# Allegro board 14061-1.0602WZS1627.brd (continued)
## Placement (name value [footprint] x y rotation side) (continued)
Q6714  LMBT3904LT1G-GP  [SOT23CBE2D4H44]  98.05 120.17 270 top
Q6715  PMBS3904-1-GP  [SOT-23-10H44]  58.51 137.68 270 top
Q9624  AO3418L-GP  [SOT23DGS2D8H50]  20.18 206.12 0 bottom
Q9625  MMBT3904-4-GP  [SOT23CBE2D4H44]  101.63 92.46 90 top
Q9628  2N7002A-7-GP  [SOT23DGS2D4H48]  116.01 83.39 90 top
Q9629  AO3413L-GP  [SOT23DGS2D8H50]  110.26 83.24 0 top
Q9632  AO3413L-GP  [SOT23DGS2D8H50]  74.95 130.2 90 top
Q9634  DMN3052L-7-GP  [SOT23DGS2D4H48]  75.61 126.56 90 top
Q9635  LMBT3904LT1G-GP  [SOT23CBE2D4H44]  64.04 137.31 180 top
Q9636  2N7002A-7-GP  [SOT23DGS2D4H48]  71.96 133.78 270 top
Q9640  AO3413L-GP  [SOT23DGS2D8H50]  80.36 129.22 180 top
Q9641  AO3413L-GP  [SOT23DGS2D8H50]  80.35 133.24 180 top
Q9642  LMBT3904LT1G-GP  [SOT23CBE2D4H44]  74.04 137.46 270 top
Q9643  MMBT3904DW-GP  [SOT-363H44]  85.77 126.7 180 top
Q9646  2N7002KDW-GP  [SOT-363H44]  139.78 8.81 0 top
Q9647  AO3413L-GP  [SOT23DGS2D8H50]  41.71 110.34 180 bottom
Q9648  2N7002A-7-GP  [SOT23DGS2D4H48]  132.07 72.46 90 bottom
Q9649  AO3413L-GP  [SOT23DGS2D8H50]  139.44 71.73 90 bottom
Q9650  2N7002A-7-GP  [SOT23DGS2D4H48]  45.49 117.08 0 bottom
R5  -  [0R0402-PAD]  156.13 196.21 270 top
R7  10KR2J-3-GP  [R402H16]  154.21 196.28 90 top
R8  330R3J-L-GP  [R603H22]  38.46 109.15 90 bottom
R10  8K2R2J-3-GP  [R402H16]  128.81 214 0 bottom
R13  39K2R2F-L-GP  [R402H16]  127.8 214 180 bottom
R14  0R2J-2-GP  [R402H16]  122.08 220.47 270 top
R15  0R0402-PAD-2-GP  [0R0402-PAD-1]  133.89 215.14 0 bottom
R19  1MR2J-1-GP  [R402H16]  35.57 109.68 0 bottom
R20  470KR2F-GP  [R402H16]  38.9 118.95 180 bottom
R22  0R0402-PAD-2-GP  [0R0402-PAD-1]  104.17 215.14 270 top
R23  0R0402-PAD-2-GP  [0R0402-PAD-1]  104.17 216.15 270 top
R24  0R3J-0-U-GP  [R603H22]  157.46 186.82 270 bottom
R26  100KR2J-1-GP  [R402H16]  36.86 119.38 90 bottom
R27  D33R6F-GP  [R1206H26]  41.94 38.48 270 bottom
R30  100KR2J-1-GP  [R402H16]  36.86 118.32 90 bottom
R32  4K7R2J-2-GP  [R402H16]  39.58 86.51 0 bottom
R33  100KR2J-1-GP  [R402H16]  35.27 115.28 0 bottom
R34  0R0402-PAD-2-GP  [0R0402-PAD-1]  155.75 187.78 0 top
R35  0R0402-PAD-2-GP  [0R0402-PAD-1]  37.37 86.49 0 bottom
R37  0R1206-PAD-1-GP  [0R1206-PAD-1]  41 31.8 270 top
R39  22R2J-2-GP  [R402H16]  34.83 115.72 270 top
R41  10KR2J-3-GP  [R402H16]  33.82 113.67 90 bottom
R42  10KR2J-3-GP  [R402H16]  33.31 115.19 0 bottom
R43  220R2F-GP  [R402H16]  159.51 183.89 270 top
R44  10KR2J-3-GP  [R402H16]  44.97 121.72 270 top
R45  100R2F-L1-GP-U  [R402H14]  31.94 25.7 180 bottom
R46  1KR2J-1-GP  [R402H16]  134.55 203.45 180 top
R47  0R0402-PAD-2-GP  [0R0402-PAD-1]  162.52 203.22 0 bottom
R48  10KR2J-3-GP  [R402H16]  97.22 127.55 90 top
R49  10KR2J-3-GP  [R402H16]  98.71 127.47 0 top
R50  10KR2J-3-GP  [R402H16]  42.96 121.72 90 top
R51  10KR2J-3-GP  [R402H16]  93.02 123.7 270 top
R53  0R0402-PAD-2-GP  [0R0402-PAD-1]  26.02 32.36 270 bottom
R54  10KR2J-3-GP  [R402H16]  92 126.5 0 top
R55  2K2R2J-2-GP  [R402H16]  105.95 69.37 0 top
R56  10KR2J-3-GP  [R402H16]  104.73 69.37 180 top
R57  10KR2J-3-GP  [R402H16]  110.7 65.56 0 bottom
R58  10KR2J-3-GP  [R402H16]  26.91 15.44 270 top
R59  10KR2J-3-GP  [R402H16]  26.91 16.47 270 top
R60  10KR2J-3-GP  [R402H16]  28.96 13.91 90 bottom
R61  1KR2F-3-GP  [R402H16]  36.02 24.33 180 bottom
R62  10KR2J-3-GP  [R402H16]  104.6 120.55 180 top
R63  10KR2J-3-GP  [R402H16]  103.7 122.31 270 top
R64  1KR2J-1-GP  [R402H16]  18.63 188.11 270 top
R65  10KR2J-3-GP  [R402H16]  31.71 179.43 0 bottom
R66  10KR2J-3-GP  [R402H16]  109.72 120.19 0 top
R67  10KR2J-3-GP  [R402H16]  109.21 123 0 top
R68  100R2F-L1-GP-U  [R402H14]  15.7 201.35 180 top
R69  4K7R2J-2-GP  [R402H16]  47.02 78.28 0 top
R71  2K2R2J-2-GP  [R402H16]  15.68 203.3 0 top
R72  2K2R2J-2-GP  [R402H16]  25.76 176.79 270 bottom
R73  20KR2J-L2-GP  [R402H16]  19.23 204.43 270 top
R74  0R0402-PAD-2-GP  [0R0402-PAD-1]  19.34 201.83 180 top
R75  10KR2J-3-GP  [R402H16]  26.2 178.31 180 bottom
R76  8K2R2F-1-GP  [R402H16]  17.18 205.51 270 top
R80  4K7R2J-2-GP  [R402H16]  16.75 207.01 0 top
R81  10MR3F-GP  [R603H22]  56.55 153.64 0 top
R82  10KR2F-2-GP  [R402H16]  30.23 22.3 180 bottom
R86  0R0402-PAD-2-GP  [0R0402-PAD-1]  153.67 171.44 90 top
R87  20KR2F-L-GP  [R402H16]  153.67 170.39 90 top
R88  -  [0R0402-PAD]  153.73 174.35 90 top
R89  10KR2J-3-GP  [R402H16]  155.84 174.35 90 top
R91  20KR2F-L-GP  [R402H16]  153.99 180.53 90 top
R92  0R2J-2-GP  [R402H16]  155.61 170.43 90 top
R94  100KR2J-1-GP  [R402H16]  153.96 191.01 180 top
R95  10KR2J-3-GP  [R402H16]  34.04 207.75 90 bottom
R101  -  [0R0805-PAD]  17.77 211.54 90 top
R117  4K7R2F-GP  [R402H16]  131.07 148.29 180 bottom
R122  4K7R2F-GP  [R402H16]  139.05 146.96 0 bottom
R131  0R2J-2-GP  [R402H16]  36.27 117.07 90 top
R132  100KR2J-1-GP  [R402H16]  38.13 23.5 90 bottom
R133  4K7R2J-2-GP  [R402H16]  39.66 25.02 0 bottom
R134  10KR2J-3-GP  [R402H16]  40.09 23.5 90 bottom
R135  4K7R2J-2-GP  [R402H16]  38.13 25.73 90 top
R138  10KR2J-3-GP  [R402H16]  41.69 28.24 270 top
R139  4K7R2J-2-GP  [R402H16]  38.13 26.87 90 top
R143  1KR2J-1-GP  [R402H16]  38.44 23.57 270 top
R144  100KR2J-1-GP  [R402H16]  37.24 24.64 270 top
R146  2KR2J-1-GP  [R402H16]  127.74 65.74 90 bottom
R149  10KR2J-3-GP  [R402H16]  127.74 66.78 270 bottom
R151  100KR2J-1-GP  [R402H16]  152.6 207.45 270 top
R152  4K7R2J-2-GP  [R402H16]  148.47 223.77 180 top
R153  100KR2J-1-GP  [R402H16]  149.19 209.62 90 top
R155  100KR2J-1-GP  [R402H16]  155.84 108.27 90 bottom
R156  10KR2J-3-GP  [R402H16]  155.34 106.83 270 bottom
R157  -  [0R0805-PAD]  155.29 112.92 270 bottom
R158  10KR2J-3-GP  [R402H16]  155.67 111.4 90 bottom
R162  100KR2J-1-GP  [R402H16]  149.95 212 270 top
R163  47KR2J-2-GP  [R402H16]  149.19 210.95 90 top
R164  10KR2J-3-GP  [R402H16]  149.95 213.04 270 top
R169  10KR2J-3-GP  [R402H16]  32.65 135.39 90 top
R172  10KR2J-3-GP  [R402H16]  36.64 135.66 0 top
R174  619R2F-L1-GP  [R402H16]  164.4 116.14 0 bottom
R178  0R0402-PAD-2-GP  [0R0402-PAD-1]  95.42 116.46 90 top
R179  0R2J-2-GP  [R402H16]  158.2 102.53 180 bottom
R180  0R2J-2-GP  [R402H16]  158.2 104.43 180 bottom
R181  100KR2J-1-GP  [R402H16]  152.59 205.49 90 top
R183  -  [0R0805-PAD]  21.19 196.15 270 top
R184  10KR2J-3-GP  [R402H16]  94.92 117.65 90 top
R185  -  [0R0805-PAD]  21.16 194.09 270 top
R186  10KR2J-3-GP  [R402H16]  40.71 128.24 0 top
R199  1KR2J-1-GP  [R402H16]  137.31 17.21 180 top
R202  2K1R2F-GP  [R402H16]  48.04 114.05 0 top
R203  2K1R2F-GP  [R402H16]  49.21 114.02 180 top
R205  0R0402-PAD-2-GP  [0R0402-PAD-1]  154.9 46.99 270 bottom
R206  0R2J-2-GP  [R402H16]  154.9 45.9 270 bottom
R207  0R0402-PAD-2-GP  [0R0402-PAD-1]  151.32 53.04 180 top
R208  47KR2F-GP  [R402H16]  151.04 56.01 0 top
R209  33R2J-2-GP  [R402H16]  152.31 45.44 90 top
R210  47KR2F-GP  [R402H16]  152.1 56.01 180 top
R212  68R2F-GP  [R402H16]  156.54 194.74 180 top
R213  10KR2J-3-GP  [R402H16]  150.86 51.31 90 top
R215  0R0603-PAD-2-GP-U  [0R0603-PAD-1-U]  160.69 51.18 0 bottom
R216  0R3J-0-U-GP  [R603H22]  86.2 36.2 270 top
R220  10R2F-L-GP  [R402H14]  165.74 45.42 90 top
R221  10KR2J-3-GP  [R402H16]  170.09 77.98 180 top
R222  0R0402-PAD-2-GP  [0R0402-PAD-1]  155.58 42.34 180 top
R223  2K2R2J-2-GP  [R402H16]  154.47 55.75 180 top
R225  1KR2J-1-GP  [R402H16]  159.04 60.33 180 top
R230  2K1R2F-GP  [R402H16]  49.18 108.33 0 top
R261  2K2R2J-2-GP  [R402H16]  165.82 49.33 270 top
R262  2K2R2J-2-GP  [R402H16]  165.79 48.21 90 top
R266  10KR2F-2-GP  [R402H16]  165.82 51.64 270 top
R267  5K1R2F-2-GP  [R402H16]  165.82 52.7 270 top
R268  20KR2F-L-GP  [R402H16]  165.67 53.82 90 top
R269  4K7R2F-GP  [R402H16]  134.22 61.14 90 bottom
R270  10KR2F-2-GP  [R402H16]  137.82 50.3 0 top
R272  2K2R2J-2-GP  [R402H16]  165.82 50.52 270 top
R273  100KR2J-1-GP  [R402H16]  134.96 54.33 0 bottom
R274  20KR2J-L2-GP  [R402H16]  132.04 56.92 270 bottom
R275  10KR2F-2-GP  [R402H16]  139.09 50.3 0 top
R277  1KR2J-1-GP  [R402H16]  144.74 64.69 180 top
R278  1KR2J-1-GP  [R402H16]  144.31 66.17 270 top
R279  10KR2F-2-GP  [R402H16]  140.36 50.3 0 top
R280  0R0402-PAD-2-GP  [0R0402-PAD-1]  129.09 58.24 90 bottom
R281  10KR2J-3-GP  [R402H16]  170.09 80.01 0 top
R283  0R0402-PAD-2-GP  [0R0402-PAD-1]  138.84 65.1 180 top
R284  10R2F-L-GP  [R402H14]  165.77 46.81 90 top
R285  10KR2J-3-GP  [R402H16]  133.69 46.66 0 top
R286  10KR2J-3-GP  [R402H16]  134.22 58.75 270 bottom
R287  1KR2J-1-GP  [R402H16]  30.28 32.16 180 top
R289  0R3J-0-U-GP  [R603H22]  136.15 46.41 180 top
R293  1KR2J-1-GP  [R402H16]  137.73 64.52 180 top
R296  10KR2J-3-GP  [R402H16]  142.35 49.43 270 top
R297  10KR2J-3-GP  [R402H16]  122.61 53.34 270 bottom
R299  243R2F-2-GP  [R402H16]  48.44 97.76 90 top
R300  0R0603-PAD-2-GP-U  [0R0603-PAD-1-U]  157.64 40.41 90 top
R301  0R0603-PAD-2-GP-U  [0R0603-PAD-1-U]  161.83 65.58 45 top
R302  5K11R2F-L1-GP  [R402H16]  81.59 83.93 180 bottom
R303  10KR2J-3-GP  [R402H16]  134.32 50.92 0 top
R304  10KR2J-3-GP  [R402H16]  132.67 46.66 0 top
R305  0R0402-PAD-2-GP  [0R0402-PAD-1]  130.59 47.35 270 top
R306  1K5R3-GP  [R603H22]  167.7 91.29 0 top
R309  33R2J-2-GP  [R402H16]  135.11 64.75 270 top
R310  10KR2J-3-GP  [R402H16]  135.19 63.37 90 top
R311  10KR2J-3-GP  [R402H16]  135.19 62.33 90 top
R312  33R2J-2-GP  [R402H16]  135.19 61.24 90 top
R313  10KR2J-3-GP  [R402H16]  135.08 58.84 90 top
R314  1KR2J-1-GP  [R402H16]  154.21 48.95 90 bottom
R316  1KR2J-1-GP  [R402H16]  135.91 51.46 90 top
R317  10KR2J-3-GP  [R402H16]  99.68 76.23 180 top
R318  0R0402-PAD-2-GP  [0R0402-PAD-1]  129.37 70.38 0 top
R319  100KR2F-L1-GP  [R402H16]  151.09 52.25 270 bottom
R320  243R2F-2-GP  [R402H16]  48.47 94.67 90 top
R321  100KR2J-1-GP  [R402H16]  135.34 75.59 270 top
R322  1MR3F-GP  [R603H22]  150.73 54.13 0 bottom
R323  10KR2J-3-GP  [R402H16]  130.94 64.07 180 bottom
R324  4K7R2J-2-GP  [R402H16]  99.68 78.13 0 top
R329  8K2R2J-3-GP  [R402H16]  28.63 12.8 270 bottom
R330  10KR2J-3-GP  [R402H16]  125.71 62.33 180 bottom
R331  1KR2J-1-GP  [R402H16]  31.39 17.95 180 top
R332  15KR2F-GP  [R402H16]  31.45 19.84 180 top
R333  10KR2J-3-GP  [R402H16]  124.7 62.33 180 bottom
R335  10KR2J-3-GP  [R402H16]  125.94 46.84 0 top
R336  1KR2J-1-GP  [R402H16]  123.68 62.33 180 bottom
R337  33R2J-2-GP  [R402H16]  128.35 70.64 180 top
R338  100KR2J-1-GP  [R402H16]  125.28 70.76 0 top
R340  10KR2J-3-GP  [R402H16]  26.42 13.44 0 bottom
R342  10KR2J-3-GP  [R402H16]  138.85 12.93 180 top
R344  0R0603-PAD-2-GP-U  [0R0603-PAD-1-U]  159.34 26.49 270 top
R345  0R0603-PAD-2-GP-U  [0R0603-PAD-1-U]  161.07 39.75 270 top
R346  0R0603-PAD-2-GP-U  [0R0603-PAD-1-U]  163.47 34 0 top
R347  3K9R2F-GP  [R402H16]  159.47 28.04 180 top
R348  10KR2J-3-GP  [R402H16]  120.81 74.37 90 top
R351  75R3F-GP  [R603H22]  134.96 10.54 0 top
R352  75R3F-GP  [R603H22]  136.2 10.54 180 top
R354  10KR2F-2-GP  [R402H16]  128 46.81 0 top
R355  10K5R3F-GP  [R603H22]  161.07 37.21 270 top
R356  0R0603-PAD-2-GP-U  [0R0603-PAD-1-U]  161.07 38.48 90 top
R357  10KR2F-2-GP  [R402H16]  160.54 28.17 180 top
R358  5K6R2F-2-GP  [R402H16]  163.3 31.47 180 top
R359  0R0603-PAD-2-GP-U  [0R0603-PAD-1-U]  164.42 38.89 90 top
R360  100KR2J-1-GP  [R402H16]  160.82 35.18 90 top
R361  100KR2J-1-GP  [R402H16]  160.54 30.07 180 top
R362  10KR2J-3-GP  [R402H16]  131.48 6.02 270 top
R363  10KR2F-2-GP  [R402H16]  116 68.15 90 bottom
R364  10KR2J-3-GP  [R402H16]  129.55 6.02 270 top
R365  10K5R3F-GP  [R603H22]  164.4 36.35 270 top
R366  10KR2F-2-GP  [R402H16]  117.85 66.04 90 bottom
R367  0R0603-PAD-2-GP-U  [0R0603-PAD-1-U]  164.4 37.64 270 top
R368  1KR2J-1-GP  [R402H16]  30.23 19.91 0 bottom
R369  1MR3F-GP  [R603H22]  36.36 9.27 270 top
R370  10KR2F-2-GP  [R402H16]  29.12 24.96 270 bottom
R372  2KR2F-3-GP  [R402H16]  35.48 18.65 90 bottom
R373  33R2J-2-GP  [R402H16]  29.12 23.93 90 bottom
R374  -  [0R0402-PAD]  40.55 9.88 0 bottom
R375  1KR2J-1-GP  [R402H16]  112.48 55.78 270 top
R376  10R3J-3-GP  [R603H22]  155.51 37.41 90 top
R377  2K49R2F-GP  [R402H16]  39.12 9.8 180 top
R378  10KR2J-3-GP  [R402H16]  43.98 10.44 270 bottom
R379  0R2J-2-GP  [R402H16]  109.28 70.19 90 top
R380  0R2J-2-GP  [R402H16]  109.24 69.09 90 top
R381  0R0402-PAD-2-GP  [0R0402-PAD-1]  110.08 67.07 180 top
R382  100R2F-L1-GP-U  [R402H14]  111.77 66.13 270 top
R385  0R0402-PAD-2-GP  [0R0402-PAD-1]  111.87 59.97 270 top
R386  0R0402-PAD-2-GP  [0R0402-PAD-1]  113.18 58.95 270 top
R388  10KR2J-3-GP  [R402H16]  119.31 69.34 90 top
R389  4K7R2J-2-GP  [R402H16]  24.49 27.1 90 bottom
R390  10KR2J-3-GP  [R402H16]  111.82 57.92 270 top
R391  10KR2J-3-GP  [R402H16]  112.12 61.04 90 bottom
R392  2K2R2J-2-GP  [R402H16]  111.87 63.02 90 top
R393  33R2J-2-GP  [R402H16]  27.36 27.13 270 bottom
R394  2KR2F-3-GP  [R402H16]  92.87 101.6 180 bottom
R395  0R0402-PAD-2-GP  [0R0402-PAD-1]  110.95 62.1 90 bottom
R396  3D3R3F-GP  [R603H22]  146.59 7.37 0 top
R397  10KR2F-2-GP  [R402H16]  116.29 56.69 90 bottom
R398  10KR2J-L-GP  [R402H15]  69.08 84.73 180 top
R399  0R0402-PAD-2-GP  [0R0402-PAD-1]  124.62 55.14 90 bottom
R400  0R0402-PAD-2-GP  [0R0402-PAD-1]  124.62 54.1 90 bottom
R403  3D3R3F-GP  [R603H22]  146.59 10.03 180 top
R404  10KR2F-2-GP  [R402H16]  119.07 54.41 180 bottom
R415  3D3R3F-GP  [R603H22]  146.59 15.49 180 top
R419  3D3R3F-GP  [R603H22]  146.59 12.83 0 top
R421  10KR2J-3-GP  [R402H16]  46.11 34.75 0 top
R422  15KR2F-GP  [R402H16]  45.6 22.07 0 top
R424  100KR2J-1-GP  [R402H16]  46.69 22.07 180 top
R426  33R2J-2-GP  [R402H16]  44.53 22.07 180 top
R428  47R2J-2-GP  [R402H16]  86.29 32.44 90 top
R429  47R2J-2-GP  [R402H16]  84.26 32.41 90 top
R430  1K5R2J-3-GP  [R402H16]  45.75 33.27 90 top
R456  51R2J-2-GP  [R402H16]  138.62 203.43 0 top
R457  51R2J-2-GP  [R402H16]  139.63 203.43 0 top
R458  51R2J-2-GP  [R402H16]  139.99 206.1 0 top
R466  51R2J-2-GP  [R402H16]  152.51 202.45 270 bottom
R473  51R2J-2-GP  [R402H16]  137.6 203.43 0 top
R477  1KR2J-1-GP  [R402H16]  153.96 192.91 0 top
R481  10KR2J-3-GP  [R402H16]  42.37 104.14 270 bottom
R482  10KR2J-3-GP  [R402H16]  44.48 92.56 0 bottom
R483  4K7R2F-GP  [R402H16]  129.5 188.06 270 bottom
R484  4K7R2F-GP  [R402H16]  125.76 182.85 0 bottom
R492  20KR2J-L2-GP  [R402H16]  63.66 148.97 270 top
R498  10KR2J-3-GP  [R402H16]  77.81 185.01 180 top
R499  10KR2J-3-GP  [R402H16]  88.53 140.64 180 top
R501  100KR2J-1-GP  [R402H16]  39.1 118.85 90 top
R502  2K2R2J-2-GP  [R402H16]  43.62 23.42 180 bottom
R503  0R2J-2-GP  [R402H16]  38.25 117.07 90 top
R505  10KR2J-3-GP  [R402H16]  41.99 20.9 270 top
R507  0R0402-PAD-2-GP  [0R0402-PAD-1]  31.53 99.75 270 bottom
R510  10KR2J-3-GP  [R402H16]  88.27 150.27 270 bottom
R511  12KR2F-L-GP  [R402H16]  31.53 98.73 90 bottom
R512  100KR2J-1-GP  [R402H16]  31.53 87.04 90 bottom
R513  402R2F-GP  [R402H16]  69.68 165.08 270 bottom
R514  10KR2J-3-GP  [R402H16]  142.27 8.09 0 top
R515  0R0402-PAD-2-GP  [0R0402-PAD-1]  47.62 76.73 90 top
R516  10KR2J-3-GP  [R402H16]  42.15 23.77 90 bottom
R517  10KR2J-3-GP  [R402H16]  53.51 78.54 270 top
R519  402R2F-GP  [R402H16]  76.44 167.72 270 bottom
R523  10KR2J-3-GP  [R402H16]  48.06 78.28 180 top
R524  49D9R2F-GP  [R402H16]  76.31 162.08 270 bottom
R527  182R2F-GP  [R402H16]  98.33 159.26 0 top
R530  10KR2J-3-GP  [R402H16]  78.05 150.06 90 bottom
R531  10KR2J-3-GP  [R402H16]  63.48 77.47 180 top
R532  0R0402-PAD-2-GP  [0R0402-PAD-1]  150.73 127.28 270 bottom
R533  10KR2J-3-GP  [R402H16]  61.95 76.81 270 top
R535  4K7R2J-2-GP  [R402H16]  55.94 77.9 90 top
R536  -  [0R0402-PAD]  77.91 148.51 0 bottom
R537  10KR2F-L1-GP  [R402H15]  100.31 158.37 180 top
R539  0R0402-PAD-2-GP  [0R0402-PAD-1]  100.24 150.5 180 top
R542  4K7R2F-GP  [R402H16]  101.73 151.21 90 top
R543  10KR2F-L1-GP  [R402H15]  100.92 149 270 top
R544  1KR2J-1-GP  [R402H16]  153.7 185.17 90 top
R545  4K7R2F-GP  [R402H16]  101.73 150.06 270 top
R549  10KR2F-L1-GP  [R402H15]  154.92 129.31 90 bottom
R550  10KR2J-3-GP  [R402H16]  100.92 147.88 270 top
R551  10KR2F-L1-GP  [R402H15]  96.83 130.16 90 top
R552  10KR2J-3-GP  [R402H16]  82.94 150.06 180 bottom
R553  10KR2J-3-GP  [R402H16]  91.6 147.07 270 bottom
R554  10KR2J-3-GP  [R402H16]  83.12 147.55 0 bottom
R555  10KR2J-3-GP  [R402H16]  82.05 142.93 180 top
R556  10KR2J-3-GP  [R402H16]  92.26 148.41 270 top
R557  10KR2J-3-GP  [R402H16]  93.07 148.98 270 bottom
R558  10KR2J-3-GP  [R402H16]  82.99 140.69 180 top
R560  10KR2J-3-GP  [R402H16]  83.42 145.77 0 top
R561  10KR2J-3-GP  [R402H16]  91.15 148.97 270 bottom
R562  10KR2J-3-GP  [R402H16]  85.07 145.82 0 top
R563  10KR2J-3-GP  [R402H16]  84.03 143.46 90 top
R565  0R2J-2-GP  [R402H16]  159.72 137.57 90 bottom
R567  10KR2J-3-GP  [R402H16]  85.5 141.1 90 top
R569  10KR2J-3-GP  [R402H16]  155.34 105.79 270 bottom
R572  1KR2J-1-GP  [R402H16]  156.07 140.54 0 bottom
R576  10KR2J-3-GP  [R402H16]  161.83 140.56 0 top
R577  -  [0R0603-PAD]  159.49 114.59 180 top
R579  10KR2J-3-GP  [R402H16]  130.61 128.4 180 bottom
R581  10KR2J-3-GP  [R402H16]  127.67 128.42 180 bottom
R617  33KR2J-3-GP  [R402H16]  148.93 45.14 180 top
R618  0R2J-2-GP  [R402H16]  150.86 50.19 270 top
R627  1KR2J-1-GP  [R402H16]  157.18 60.4 180 top
R634  4K7R2J-2-GP  [R402H16]  153.96 39.09 270 bottom
R635  1KR2J-1-GP  [R402H16]  152.81 40.13 270 top
R636  10KR2J-3-GP  [R402H16]  152.03 39.09 90 bottom
R637  10KR2J-3-GP  [R402H16]  135.08 59.87 90 top
R639  20KR2J-L2-GP  [R402H16]  148.24 37.03 270 bottom
R642  2K2R2J-2-GP  [R402H16]  89.09 144.58 180 top
R643  20KR2J-L2-GP  [R402H16]  148.24 35.99 270 bottom
R644  330R3J-L-GP  [R603H22]  119.18 63.57 270 bottom
R645  10KR2J-3-GP  [R402H16]  85.06 132.82 180 top
R646  1KR2J-1-GP  [R402H16]  86.19 132.8 0 top
R648  17K8R2F-GP  [R402H16]  112.63 53.44 90 bottom
R649  6K49R2F-1-GP  [R402H16]  112.63 54.46 90 bottom
R650  17K8R2F-GP  [R402H16]  109.71 59.92 90 bottom
R651  0R0402-PAD-2-GP  [0R0402-PAD-1]  124.62 56.18 90 bottom
R652  0R0402-PAD-2-GP  [0R0402-PAD-1]  135.99 7.01 180 top
R653  10KR2F-2-GP  [R402H16]  110.4 49.56 90 top
R655  10KR2F-2-GP  [R402H16]  112.63 51.41 90 bottom
R656  10KR2F-2-GP  [R402H16]  112.63 56.49 90 bottom
R657  10KR2F-2-GP  [R402H16]  112.25 54.71 270 top
R658  10KR2F-2-GP  [R402H16]  116.29 57.84 90 bottom
R659  4K7R2J-2-GP  [R402H16]  134.96 7.06 180 top
R661  0R2J-2-GP  [R402H16]  133.41 7.14 270 top
R662  0R2J-2-GP  [R402H16]  111.87 62 90 top
R663  0R2J-2-GP  [R402H16]  137.46 12.84 0 top
R664  0R0402-PAD-2-GP  [0R0402-PAD-1]  76 141.91 270 top
R665  4K7R2J-2-GP  [R402H16]  133.41 6.1 270 top
R667  75R3F-GP  [R603H22]  137.45 10.54 180 top
R668  0R0402-PAD-2-GP  [0R0402-PAD-1]  111.87 60.99 90 top
R669  4K7R2J-2-GP  [R402H16]  123.18 67.54 90 bottom
R673  75R3F-GP  [R603H22]  136.69 8.59 90 top
R675  10KR2J-3-GP  [R402H16]  37.05 9.55 180 bottom
R676  100KR2J-1-GP  [R402H16]  116.06 60.15 270 bottom
R677  1KR2J-1-GP  [R402H16]  114.05 66.32 180 top
R680  1KR2J-1-GP  [R402H16]  24.52 26.04 270 bottom
R681  33R2J-2-GP  [R402H16]  27.36 26.06 270 bottom
R682  -  [0R0402-PAD]  24.52 24.99 90 bottom
R689  33R2J-2-GP  [R402H16]  27.36 28.17 270 bottom
R693  4K7R2J-2-GP  [R402H16]  25.46 29.39 90 bottom
R701  0R2J-2-GP  [R402H16]  45.4 6.07 180 bottom
R702  8K2R2J-3-GP  [R402H16]  46.41 6.07 180 bottom
R704  10KR2J-3-GP  [R402H16]  42.07 9.45 270 bottom
R705  8K2R2J-3-GP  [R402H16]  47.2 9.37 90 top
R706  39K2R2F-L-GP  [R402H16]  44.98 7.98 0 top
R707  10KR2J-3-GP  [R402H16]  41.77 5.82 270 top
R709  10KR2J-3-GP  [R402H16]  95.16 29.34 180 top
R717  10KR2J-3-GP  [R402H16]  100.92 121.46 90 top
R719  10KR2J-3-GP  [R402H16]  9.71 218.19 180 top
R720  4K7R2J-2-GP  [R402H16]  12.38 224.1 270 top
R721  2K2R2J-2-GP  [R402H16]  8.87 223.52 180 top
R722  10KR2J-3-GP  [R402H16]  6.59 223.04 0 top
R725  0R0402-PAD-2-GP  [0R0402-PAD-1]  141.31 46.33 0 top
R729  0R0402-PAD-2-GP  [0R0402-PAD-1]  153.88 178.18 90 top
R739  10KR2J-3-GP  [R402H16]  40.09 8.33 270 bottom
R870  243R2F-2-GP  [R402H16]  48.57 110.71 270 bottom
R885  2K1R2F-GP  [R402H16]  49.18 108.33 180 bottom
R886  2K1R2F-GP  [R402H16]  47.25 108.33 0 bottom
R899  243R2F-2-GP  [R402H16]  48.7 106.78 270 bottom
R924  2K1R2F-GP  [R402H16]  63.41 104.52 0 bottom
R928  2K1R2F-GP  [R402H16]  62.39 104.52 180 bottom
R935  4K53R2F-1-GP  [R402H16]  99.88 101.4 180 top
R940  2KR2F-3-GP  [R402H16]  102.17 101.24 0 top
R943  8K45R2F-2-GP  [R402H16]  95.34 103.4 270 bottom
R945  2K1R2F-GP  [R402H16]  49.13 96.29 0 bottom
R946  2K1R2F-GP  [R402H16]  48.08 96.26 180 bottom
R948  4K75R2F-1-GP  [R402H16]  93.02 103.58 0 bottom
R963  10KR2J-L-GP  [R402H15]  68.05 84.73 180 top
R1074  100KR2J-1-GP  [R402H16]  31.53 91.24 90 bottom
R1079  100KR2J-1-GP  [R402H16]  31.53 94.11 270 bottom
R1126  100KR2J-1-GP  [R402H16]  112.95 79.97 270 top
R1129  8K2R2J-3-GP  [R402H16]  112.98 81.41 270 top
R1154  0R2J-2-GP  [R402H16]  106.59 202.84 270 top
R1155  0R2J-2-GP  [R402H16]  104.17 218.19 270 top
R1158  1KR2F-3-GP  [R402H16]  81.87 92.71 90 bottom
R1159  10KR2J-L-GP  [R402H15]  99.4 106.78 0 top
R1160  -  [0R0402-PAD]  98.35 106.79 0 top
R1161  1K69R2F-2-GP  [R402H16]  85.97 112.65 0 bottom
R1162  1KR2F-3-GP  [R402H16]  87.02 112.64 0 bottom
R1163  1KR2F-3-GP  [R402H16]  42.36 105.52 270 bottom
R1164  100KR2J-1-GP  [R402H16]  72.22 115.47 0 top
R1165  0R0402-PAD-2-GP  [0R0402-PAD-1]  98.74 96.37 270 top
R1166  0R0402-PAD-2-GP  [0R0402-PAD-1]  97.54 93.32 270 top
R1167  10KR2J-3-GP  [R402H16]  107.5 79.17 90 top
R1168  33R2J-2-GP  [R402H16]  107.5 80.21 270 top
R1169  33R2J-2-GP  [R402H16]  107.5 81.28 270 top
R1170  33R2J-2-GP  [R402H16]  91.98 83.57 270 top
R1171  33R2J-2-GP  [R402H16]  93.94 84.1 270 top
R1182  0R0603-PAD-2-GP-U  [0R0603-PAD-1-U]  170.92 82.37 0 top
R1193  0R0603-PAD-2-GP-U  [0R0603-PAD-1-U]  154.39 59.44 90 top
R1195  39K2R2F-L-GP  [R402H16]  113.55 84.01 180 top
R1200  40D2R2F-GP  [R402H16]  76.87 114.73 180 bottom
R1201  120R2F-GP  [R402H16]  79.81 110.22 180 bottom
R1202  10R2F-L-GP  [R402H14]  84.13 89.9 180 bottom
R1203  0R0402-PAD-2-GP  [0R0402-PAD-1]  152.26 22.38 270 top
R1204  2K2R2J-2-GP  [R402H16]  85.17 87.99 180 bottom
R1205  4K99R2F-L-GP  [R402H16]  83.11 89.9 180 bottom
R1206  51D1R2F-GP  [R402H16]  77.55 81.78 0 top
R1207  51D1R2F-GP  [R402H16]  76.54 81.78 0 top
R1208  10KR2J-3-GP  [R402H16]  88.02 144.58 180 top
R1209  0R0402-PAD-2-GP  [0R0402-PAD-1]  104.17 217.17 90 top
R1210  249R2F-GP  [R402H16]  91.47 95.98 90 bottom
R1211  499R2F-2-GP  [R402H16]  91.47 94.54 270 bottom
R1214  0R0402-PAD-2-GP  [0R0402-PAD-1]  98.33 154.69 180 top
R1215  4K7R2F-GP  [R402H16]  98.33 152.65 180 top
R1216  4K7R2F-GP  [R402H16]  99.47 154.69 180 top
R1217  182R2F-GP  [R402H16]  99.47 152.65 0 top
R1223  -  [0R0805-PAD]  91.02 200.2 90 top
R1224  -  [0R0805-PAD]  91.02 198.22 90 top
R1225  -  [0R0805-PAD]  91.02 202.36 90 top
R1226  10KR2J-3-GP  [R402H16]  78.24 186.51 90 top
R1227  402R2F-GP  [R402H16]  73.1 174.41 270 bottom
R1228  402R2F-GP  [R402H16]  73.57 170.18 90 bottom
R1230  150R2F-1-GP  [R402H16]  77.26 174.6 270 bottom
R1234  0R2J-2-GP  [R402H16]  78.27 181.64 180 top
R1236  402R2F-GP  [R402H16]  72.8 168.91 90 bottom
R1239  200KR2F-L-GP  [R402H16]  55.89 162.97 0 top
R1240  0R0402-PAD-2-GP  [0R0402-PAD-1]  57.08 163.55 180 top
R1241  0R0402-PAD-2-GP  [0R0402-PAD-1]  57.74 161.62 0 top
R1242  2K49R2F-GP  [R402H16]  75.22 160.96 270 bottom
R1244  -  [0R0603-PAD]  92.66 161.96 90 bottom
R1245  -  [0R0603-PAD]  94.44 167.04 180 bottom
R1246  0R3J-0-U-GP  [R603H22]  67.78 144.9 90 top
R1247  -  [0R0603-PAD]  71.97 145.16 270 top
R1248  0R3J-0-U-GP  [R603H22]  86.22 146.38 90 bottom
R1249  0R3J-0-U-GP  [R603H22]  86.22 147.6 90 bottom
R1250  -  [0R0603-PAD]  79.14 148.09 0 bottom
R1251  -  [0R0603-PAD]  94.62 147.41 90 top
R1252  -  [0R0603-PAD]  77.2 179.9 225 bottom
R1253  -  [0R0603-PAD]  75.12 151.66 0 bottom
R1254  -  [0R0603-PAD]  71.35 150.91 90 bottom
R1255  -  [0R0603-PAD]  70.98 153.46 270 bottom
R1256  -  [0R0603-PAD]  65.11 158.75 0 top
R1257  10KR2J-3-GP  [R402H16]  74.48 155.43 0 bottom
R1258  0R0402-PAD-2-GP  [0R0402-PAD-1]  82.05 206.25 180 bottom
R1259  100R2F-L1-GP-U  [R402H14]  77.45 151.56 0 bottom
R1260  0R2J-2-GP  [R402H16]  109.79 62.38 0 top
R1261  0R2J-2-GP  [R402H16]  56.52 151.26 0 top
R1262  10KR2J-3-GP  [R402H16]  66.66 148.39 90 top
R1263  0R0402-PAD-2-GP  [0R0402-PAD-1]  73.25 157.13 90 bottom
R1264  0R0402-PAD-2-GP  [0R0402-PAD-1]  103.69 69.37 0 top
R1265  10KR2J-3-GP  [R402H16]  66.66 149.43 270 top
R1266  10KR2J-3-GP  [R402H16]  136.56 203.43 0 top
R1267  0R2J-2-GP  [R402H16]  67.83 156.79 180 top
R1268  0R2J-2-GP  [R402H16]  77.22 181.66 0 top
R1557  100KR2F-L1-GP  [R402H16]  103.56 198.35 180 bottom
R1558  100KR2F-L1-GP  [R402H16]  109.86 200.76 270 top
R1559  100KR2F-L1-GP  [R402H16]  106.71 200 270 top
R1560  100KR2F-L1-GP  [R402H16]  155.61 185.17 270 top
R1561  100KR2F-L1-GP  [R402H16]  91.22 200.51 180 bottom
R1562  4K7R2F-GP  [R402H16]  103.11 197.89 0 top
R1565  4K7R2F-GP  [R402H16]  96.22 198.42 180 bottom
R1568  10KR2J-3-GP  [R402H16]  141.1 206.12 0 top
R1569  0R0402-PAD-2-GP  [0R0402-PAD-1]  152.51 200.43 270 bottom
R1570  4K7R2F-GP  [R402H16]  101.33 197.89 0 top
R1571  0R0402-PAD-2-GP  [0R0402-PAD-1]  99.83 73.23 90 top
R1576  0R2J-2-GP  [R402H16]  94.05 129.58 180 top
R1577  0R2J-2-GP  [R402H16]  77.86 211.18 0 top
R1578  0R2J-2-GP  [R402H16]  89.04 129.62 180 top
R1579  10KR2J-3-GP  [R402H16]  90.34 123.61 90 top
R1580  10KR2J-3-GP  [R402H16]  90.95 126.49 0 top
R1581  10KR2J-3-GP  [R402H16]  90.59 130.03 90 top
R1582  10KR2J-3-GP  [R402H16]  92.52 130.03 90 top
R1584  0R0402-PAD-2-GP  [0R0402-PAD-1]  87.28 213.61 270 top
R1585  0R0402-PAD-2-GP  [0R0402-PAD-1]  87.28 215.9 270 top
R1586  0R0402-PAD-2-GP  [0R0402-PAD-1]  87.28 214.76 270 top
R1587  0R0402-PAD-2-GP  [0R0402-PAD-1]  87.28 217.04 270 top
R1588  0R0402-PAD-2-GP  [0R0402-PAD-1]  21.2 170.7 0 top
R1589  0R0402-PAD-2-GP  [0R0402-PAD-1]  22.28 169.93 0 top
R1591  0R2J-2-GP  [R402H16]  135.11 65.79 270 top
R1592  0R0402-PAD-2-GP  [0R0402-PAD-1]  112.48 56.85 90 top
R1593  0R0402-PAD-2-GP  [0R0402-PAD-1]  39.95 137.06 0 top
R1596  0R0402-PAD-2-GP  [0R0402-PAD-1]  154.8 21.79 270 top
R1597  0R0402-PAD-2-GP  [0R0402-PAD-1]  155.13 25.35 90 top
R1598  0R0402-PAD-2-GP  [0R0402-PAD-1]  159.16 36.5 180 top
R1599  0R0402-PAD-2-GP  [0R0402-PAD-1]  94.78 33.15 180 top
R1601  0R0402-PAD-2-GP  [0R0402-PAD-1]  102.36 131.02 90 top
R1602  0R0402-PAD-2-GP  [0R0402-PAD-1]  45.75 32.13 270 top
R1604  0R0402-PAD-2-GP  [0R0402-PAD-1]  82.3 210.69 270 bottom
R1606  0R0402-PAD-2-GP  [0R0402-PAD-1]  18.98 165.63 90 top
R1608  0R0402-PAD-2-GP  [0R0402-PAD-1]  104.17 213.11 270 top
R1609  0R0402-PAD-2-GP  [0R0402-PAD-1]  104.17 214.12 270 top
R1610  0R0402-PAD-2-GP  [0R0402-PAD-1]  104.17 211.07 270 top
R1611  0R0402-PAD-2-GP  [0R0402-PAD-1]  104.17 212.09 270 top
R1612  0R0402-PAD-2-GP  [0R0402-PAD-1]  104.17 219.2 270 top
R1615  10KR2J-3-GP  [R402H16]  133.89 219.2 0 bottom
R1620  0R2J-2-GP  [R402H16]  122.08 218.44 270 top
R1621  0R2J-2-GP  [R402H16]  122.13 217.4 270 top
R1622  0R2J-2-GP  [R402H16]  122.08 219.46 270 top
R1623  0R2J-2-GP  [R402H16]  122.08 221.49 270 top
R1627  0R0402-PAD-2-GP  [0R0402-PAD-1]  122.09 221.48 90 bottom
R1628  0R0402-PAD-2-GP  [0R0402-PAD-1]  104.17 220.22 270 top
R1633  10KR2J-3-GP  [R402H16]  120.3 206.38 0 bottom
R1634  0R5J-5-GP  [R805H24]  130.08 209.8 180 bottom
R1637  0R0402-PAD-2-GP  [0R0402-PAD-1]  106.59 203.89 90 top
R1647  20R2F-GP  [R402H16]  18.99 163.53 90 top
R1648  49D9R2F-GP  [R402H16]  17.51 163.09 0 top
R1653  20R2F-GP  [R402H16]  78.52 210.69 0 bottom
R1654  49D9R2F-GP  [R402H16]  77.38 210.69 0 bottom
R1656  10KR2J-3-GP  [R402H16]  163.79 140.53 0 top
R1661  10KR2J-3-GP  [R402H16]  66.24 143.32 180 top
R1668  0R0402-PAD-2-GP  [0R0402-PAD-1]  95.6 123.06 0 top
R1669  0R0402-PAD-2-GP  [0R0402-PAD-1]  101.63 129.11 0 top
R1670  0R0402-PAD-2-GP  [0R0402-PAD-1]  129.5 189.15 90 bottom
R1671  0R0402-PAD-2-GP  [0R0402-PAD-1]  140.58 146.53 90 bottom
R1672  0R0402-PAD-2-GP  [0R0402-PAD-1]  138.72 183.11 0 bottom
R1683  0R0402-PAD-2-GP  [0R0402-PAD-1]  153.03 214.2 180 top
R1687  8K2R2J-3-GP  [R402H16]  92.31 131.77 270 top
R1688  8K2R2J-3-GP  [R402H16]  100.57 119.02 180 top
R1689  0R0402-PAD-2-GP  [0R0402-PAD-1]  22.54 177.37 90 top
R1696  100KR2J-1-GP  [R402H16]  163.38 133.17 90 top
R1697  0R2J-2-GP  [R402H16]  88.86 142.65 180 top
R1714  10R2J-2-GP  [R402H14]  42.84 127.63 0 top
R1719  10KR2J-3-GP  [R402H16]  29.93 12.27 0 top
R1720  0R3J-0-U-GP  [R603H22]  24.68 5.69 270 bottom
R1729  10R2J-2-GP  [R402H14]  41.81 128.27 0 top
R1730  10R2J-2-GP  [R402H14]  34.95 137.66 90 top
R1731  10R2J-2-GP  [R402H14]  34.98 136.52 90 top
R1732  10R2J-2-GP  [R402H14]  43.33 124.58 0 top
R1733  33R2J-2-GP  [R402H16]  38.24 135.23 270 top
R1734  56D2R2F  [R402H16]  80.81 210.69 0 bottom
R1738  1KR2J-1-GP  [R402H16]  149.87 191.49 0 bottom
R1739  1KR2J-1-GP  [R402H16]  148.93 188.16 90 bottom
R1740  1KR2J-1-GP  [R402H16]  151.11 190.63 0 bottom
R1741  1KR2J-1-GP  [R402H16]  150.5 188.67 180 bottom
R1742  1KR2J-1-GP  [R402H16]  128.1 216.48 90 bottom
R1743  1KR2J-1-GP  [R402H16]  127.95 221.44 90 bottom
R1744  1KR2J-1-GP  [R402H16]  138.03 192.1 270 bottom
R1745  1KR2J-1-GP  [R402H16]  138.08 193.19 270 bottom
R1746  51R2J-2-GP  [R402H16]  161.96 179.02 270 top
R1747  0R0402-PAD-2-GP  [0R0402-PAD-1]  100.69 56.67 270 top
R1776  0R0402-PAD-2-GP  [0R0402-PAD-1]  100.69 57.81 270 top
R1778  0R0402-PAD-2-GP  [0R0402-PAD-1]  156.83 94.69 180 bottom
R1779  45D3R2F-L-GP  [R402H16]  71.23 171.51 90 bottom
R1780  10KR2J-3-GP  [R402H16]  94.79 148.77 90 top
R1782  10KR2J-3-GP  [R402H16]  104.68 221.74 180 top
R1784  470R2F-GP  [R402H16]  43.56 184.18 270 bottom
R1785  470R2F-GP  [R402H16]  50.36 182.75 90 bottom
R1786  470R2F-GP  [R402H16]  87.29 218.12 270 top
R1787  470R2F-GP  [R402H16]  50.58 179.12 90 bottom
R1788  470R2F-GP  [R402H16]  50.76 219.66 180 bottom
R1789  470R2F-GP  [R402H16]  42.22 179.17 270 top
R1790  470R2F-GP  [R402H16]  41.54 184.02 180 bottom
R1791  0R2J-2-GP  [R402H16]  66.69 177.62 270 top
R1792  1KR2J-1-GP  [R402H16]  88.17 147.73 180 bottom
R1793  1KR2J-1-GP  [R402H16]  85.38 148.72 270 bottom
R1794  1KR2J-1-GP  [R402H16]  85.12 150.19 180 bottom
R1795  1KR2J-1-GP  [R402H16]  87.41 140.64 0 top
R1796  1KR2J-1-GP  [R402H16]  85.33 142.16 270 top
R1797  1KR2J-1-GP  [R402H16]  84.03 140.69 0 top
R1798  1KR2J-1-GP  [R402H16]  81.95 139.55 0 top
R1799  1KR2J-1-GP  [R402H16]  80.88 139.55 0 top
R1800  1KR2J-1-GP  [R402H16]  79.84 139.55 0 top
R1801  10KR2F-2-GP  [R402H16]  103.11 195.86 0 top
R1802  10KR2F-2-GP  [R402H16]  101.33 195.86 0 top
R1803  10KR2F-2-GP  [R402H16]  101.89 198.35 180 bottom
R1804  10KR2F-2-GP  [R402H16]  101.89 200.38 180 bottom
R1805  10KR2F-2-GP  [R402H16]  100.01 200.41 180 bottom
R1806  10KR2F-2-GP  [R402H16]  100.01 198.37 180 bottom
R1807  10KR2F-2-GP  [R402H16]  91.22 198.48 180 bottom
R1808  10KR2F-2-GP  [R402H16]  104.3 195.83 0 top
R1809  10KR2F-2-GP  [R402H16]  104.3 197.87 0 top
R1810  10KR2F-2-GP  [R402H16]  98.28 200.43 180 bottom
R1811  10KR2F-2-GP  [R402H16]  98.28 198.4 180 bottom
R1812  10KR2F-2-GP  [R402H16]  96.22 200.46 180 bottom
R1813  10KR2F-2-GP  [R402H16]  94.8 200.48 180 bottom
R1814  10KR2F-2-GP  [R402H16]  94.8 198.45 180 bottom
R1815  10KR2F-2-GP  [R402H16]  92.72 200.48 180 bottom
R1816  10KR2F-2-GP  [R402H16]  92.72 198.45 180 bottom
R1817  10KR2F-2-GP  [R402H16]  108.21 200.41 180 bottom
R1818  10KR2F-2-GP  [R402H16]  103.56 200.38 180 bottom
R1819  10KR2F-2-GP  [R402H16]  109.3 200.41 180 bottom
R1820  10KR2J-3-GP  [R402H16]  152.76 204.11 90 top
R1822  100R2F-L1-GP-U  [R402H14]  85.06 212.01 180 top
R1823  100R2F-L1-GP-U  [R402H14]  84.36 215.65 270 top
R1826  100R2F-L1-GP-U  [R402H14]  20.11 170.7 0 top
R1827  100R2F-L1-GP-U  [R402H14]  23.32 169.93 180 top
R1830  20KR2J-L2-GP  [R402H16]  18.98 166.7 90 top
R1831  20KR2J-L2-GP  [R402H16]  20.84 163.78 0 top
R1832  100KR2J-1-GP  [R402H16]  163.38 131.04 90 top
R1835  0R0402-PAD-2-GP  [0R0402-PAD-1]  135.39 108.61 270 top
R1836  0R0402-PAD-2-GP  [0R0402-PAD-1]  35.85 180.59 0 bottom
R1837  0R0402-PAD-2-GP  [0R0402-PAD-1]  34.32 184.78 270 bottom
R1838  0R0402-PAD-2-GP  [0R0402-PAD-1]  80.13 220.97 90 top
R1839  0R0402-PAD-2-GP  [0R0402-PAD-1]  43.8 177.25 180 top
R1840  0R2J-2-GP  [R402H16]  48.4 223.08 270 top
R1841  0R2J-2-GP  [R402H16]  45.69 223.08 90 top
R1842  10KR2J-3-GP  [R402H16]  101.47 219.09 270 top
R1843  10KR2J-3-GP  [R402H16]  104.68 223.65 180 top
R1844  2K2R2J-2-GP  [R402H16]  107.81 223.22 0 bottom
R1845  20KR2J-L2-GP  [R402H16]  63.38 174.4 0 top
R1846  0R2J-2-GP  [R402H16]  64.39 174.4 0 top
R1867  10KR2J-3-GP  [R402H16]  111.84 48.11 0 top
R1868  10KR2J-3-GP  [R402H16]  113.55 47.35 270 top
R1870  10KR2J-3-GP  [R402H16]  116.8 46.86 90 top
R1879  1MR3F-GP  [R603H22]  98.48 109.71 180 top
R1880  10KR2J-3-GP  [R402H16]  103.46 100.66 180 top
R1881  10KR2J-3-GP  [R402H16]  102.01 98.81 270 top
R1882  10KR2J-3-GP  [R402H16]  81.59 82.02 180 top
R1883  4K7R2J-2-GP  [R402H16]  100.46 104.83 0 top
R1884  33R2J-2-GP  [R402H16]  97.06 89.41 180 top
R1885  10KR2J-3-GP  [R402H16]  97.57 87.88 270 top
R1886  10KR2J-3-GP  [R402H16]  81.59 83.93 0 top
R1887  10KR2J-3-GP  [R402H16]  97.59 85.45 270 top
R1888  100R2F-L1-GP-U  [R402H14]  79.03 112.27 270 bottom
R1889  100R2F-L1-GP-U  [R402H14]  75.15 113.59 90 bottom
R1890  40D2R2F-GP  [R402H16]  77.93 114.73 180 bottom
R1891  0R0402-PAD-2-GP  [0R0402-PAD-1]  151.75 132.44 270 bottom
R1892  0R2J-2-GP  [R402H16]  79.48 181.66 180 top
R1893  10KR2J-L-GP  [R402H15]  79.3 83.16 180 bottom
R1894  100KR2J-1-GP  [R402H16]  100.59 86.33 270 top
R1895  10KR2J-L-GP  [R402H15]  70.12 84.73 180 top
R1896  47KR2F-GP  [R402H16]  99.09 89.41 180 top
R1897  1KR2F-3-GP  [R402H16]  82.61 83.93 180 bottom
R1899  4K75R2F-1-GP  [R402H16]  98.2 99.72 90 top
R1900  8K45R2F-2-GP  [R402H16]  98.2 100.74 90 top
R1905  2K1R2F-GP  [R402H16]  47.02 108.33 180 top
R1906  40D2R2F-GP  [R402H16]  48.7 111.26 270 top
R1907  40D2R2F-GP  [R402H16]  48.7 112.37 270 top
R1908  40D2R2F-GP  [R402H16]  48.44 92.81 270 top
R1909  40D2R2F-GP  [R402H16]  48.44 91.66 270 top
R1910  10KR2J-3-GP  [R402H16]  78.24 187.61 270 top
R1911  2K1R2F-GP  [R402H16]  46.77 96.14 0 top
R1914  100KR2J-1-GP  [R402H16]  74.46 115.16 270 top
R1915  10KR2J-3-GP  [R402H16]  78.95 118.31 0 top
R1916  0R0402-PAD-2-GP  [0R0402-PAD-1]  78.96 116.33 0 top
R1917  1KR2J-1-GP  [R402H16]  84.16 118.08 0 top
R1918  470KR2F-GP  [R402H16]  72.65 116.94 270 top
R1919  1MR2J-1-GP  [R402H16]  77.81 119.2 180 top
R1920  0R2J-2-GP  [R402H16]  98.71 92.2 270 top
R1921  2K1R2F-GP  [R402H16]  48.29 91.19 0 bottom
R1922  2K1R2F-GP  [R402H16]  49.31 91.19 180 bottom
R1923  2K1R2F-GP  [R402H16]  48.44 93.82 270 bottom
R1924  2K1R2F-GP  [R402H16]  48.31 92.81 90 bottom
R1984  0R0402-PAD-2-GP  [0R0402-PAD-1]  34.21 117.07 270 top
R1985  0R0402-PAD-2-GP  [0R0402-PAD-1]  38.13 27.94 90 top
R2079  0R2J-2-GP  [R402H16]  44.79 74.27 90 bottom
R2080  0R0402-PAD-2-GP  [0R0402-PAD-1]  49.33 74.32 90 bottom
R3586  0R0402-PAD-2-GP  [0R0402-PAD-1]  126.54 41.08 0 top
R5290  10KR2J-3-GP  [R402H16]  43.54 183.09 270 bottom
R6701  0R3J-0-U-GP  [R603H22]  88.15 81.41 270 top
R6702  10KR2J-3-GP  [R402H16]  88.98 79.83 0 top
R6703  100KR2J-1-GP  [R402H16]  21.72 185.78 180 top
R6704  100KR2J-1-GP  [R402H16]  88.7 74.96 270 top
R6705  100KR2J-1-GP  [R402H16]  20.25 190.2 0 top
R6706  0R2J-2-GP  [R402H16]  16.02 185.8 0 top
R79612  75R3F-GP  [R603H22]  63.28 11.94 270 top
R79618  0R0402-PAD-2-GP  [0R0402-PAD-1]  84.64 25.07 0 top
R79621  10KR2F-2-GP  [R402H16]  38.13 26.42 270 bottom
R79622  D33R6F-GP  [R1206H26]  41.94 36.2 270 bottom
R79623  300KR2F-GP  [R402H16]  38.2 27.5 270 bottom
R79625  10KR2F-2-GP  [R402H16]  41.7 30.19 90 top
R79627  300KR2F-GP  [R402H16]  38.79 29.72 180 top
R79628  100KR2F-L1-GP  [R402H16]  34.07 24.31 180 bottom
R79630  200R5J-GP  [R805H24]  34.75 35.18 180 bottom
R79631  0R1206-PAD-1-GP  [0R1206-PAD-1]  42.15 40.28 270 top
R79633  0R0402-PAD-2-GP  [0R0402-PAD-1]  34.81 25.15 0 top
R79634  0R0402-PAD-2-GP  [0R0402-PAD-1]  33.74 25.12 0 top
R79656  100R2F-L1-GP-U  [R402H14]  45.27 109.02 180 bottom
R79657  10KR2J-3-GP  [R402H16]  42.46 119.91 180 bottom
R79658  80D6R2F-L-GP  [R402H16]  77.15 154.58 180 bottom
R79659  10KR2J-3-GP  [R402H16]  161.01 125.32 180 top
R79660  0R0402-PAD-2-GP  [0R0402-PAD-1]  159.95 125.32 180 top
R79661  1KR2F-3-GP  [R402H16]  43.56 119.91 180 bottom
R79662  10KR2J-3-GP  [R402H16]  79.39 143.2 180 top
R79664  0R2J-2-GP  [R402H16]  32.6 61.17 270 bottom
R79665  0R2J-2-GP  [R402H16]  32.91 58.84 0 bottom
R79666  10KR2J-3-GP  [R402H16]  126.96 46.84 0 top
R79667  10KR2J-3-GP  [R402H16]  127.77 53.77 270 bottom
R79668  0R0402-PAD-2-GP  [0R0402-PAD-1]  36.1 86.49 0 bottom
R79669  4K7R2J-2-GP  [R402H16]  42.25 79.43 180 bottom
R79670  4K7R2J-2-GP  [R402H16]  61.95 77.93 270 top
R79673  4K7R2J-2-GP  [R402H16]  35.09 86.49 0 bottom
R79675  1KR2J-1-GP  [R402H16]  31.53 89.15 90 bottom
R79677  4K7R2J-2-GP  [R402H16]  31.54 84.02 270 bottom
R79678  4K7R2J-2-GP  [R402H16]  31.53 85.06 270 bottom
R79679  4K7R2J-2-GP  [R402H16]  30.26 77.29 180 bottom
R79680  10KR2J-3-GP  [R402H16]  31.54 88.09 90 bottom
R79681  100KR2J-1-GP  [R402H16]  31.53 90.17 90 bottom
R79682  0R2J-2-GP  [R402H16]  42.82 114.59 180 top
R79683  10KR2J-3-GP  [R402H16]  53.51 77.44 270 top
R79684  0R0402-PAD-2-GP  [0R0402-PAD-1]  44.8 75.41 90 bottom
R79685  0R0402-PAD-2-GP  [0R0402-PAD-1]  45.07 77.55 90 bottom
R79686  4K7R2J-2-GP  [R402H16]  44.41 78.33 0 top
R79687  10KR2J-3-GP  [R402H16]  51.21 75.74 270 top
R79688  10KR2J-3-GP  [R402H16]  87.32 139.05 90 top
R79689  10KR2J-3-GP  [R402H16]  132.04 64.07 180 bottom
R79690  2K2R2J-2-GP  [R402H16]  83.95 132.82 180 top
R79691  -  [0R0603-PAD]  134.88 46.41 0 top
R79692  10KR2F-2-GP  [R402H16]  139.66 60.3 180 top
R79693  10KR2F-2-GP  [R402H16]  140.88 60.3 180 top
R79694  10KR2F-2-GP  [R402H16]  142.1 60.3 180 top
R79697  0R2J-2-GP  [R402H16]  142.82 78.59 90 bottom
R79698  0R2J-2-GP  [R402H16]  145.6 80.87 270 top
R79699  0R2J-2-GP  [R402H16]  145.6 81.99 270 top
R79700  0R2J-2-GP  [R402H16]  145.58 83.11 270 top
R79701  10KR2J-3-GP  [R402H16]  161.55 109.28 0 top
R79702  10KR2J-3-GP  [R402H16]  158.8 108.38 90 top
R79703  10KR2J-3-GP  [R402H16]  159.44 107.24 270 bottom
R79704  10KR2J-3-GP  [R402H16]  121.98 47.07 0 top
R79705  10KR2J-3-GP  [R402H16]  120.91 47.07 0 top
R79707  0R5J-5-GP  [R805H24]  59.85 37.72 90 bottom
R79708  0R5J-5-GP  [R805H24]  58.15 47.05 270 top
R79709  0R5J-5-GP  [R805H24]  59.85 39.75 90 bottom
R79710  0R5J-5-GP  [R805H24]  59.85 41.78 90 bottom
R79711  0R5J-5-GP  [R805H24]  59.85 43.81 90 bottom
R79712  0R0402-PAD-2-GP  [0R0402-PAD-1]  27.92 32.82 270 bottom
R79713  0R0402-PAD-2-GP  [0R0402-PAD-1]  27.92 31.6 270 bottom
R79714  0R5J-5-GP  [R805H24]  38.01 35.15 180 bottom
R79715  0R0402-PAD-2-GP  [0R0402-PAD-1]  26.02 30.96 270 bottom
R79716  10R2F-L-GP  [R402H14]  38.2 30.99 90 bottom
R79717  1KR2J-1-GP  [R402H16]  33.69 31.72 180 top
R79718  1KR2J-1-GP  [R402H16]  30.51 29.16 180 top
R79719  10KR2J-3-GP  [R402H16]  31.5 32.61 180 top
R79720  10KR2J-3-GP  [R402H16]  29.63 30.7 90 top
R79721  10KR2J-3-GP  [R402H16]  32.55 32.61 180 top
R79722  100KR2F-L1-GP  [R402H16]  147.94 73.55 90 bottom
R79723  100KR2J-1-GP  [R402H16]  146 32.64 90 bottom
R79724  470R2J-2-GP  [R402H16]  138.95 31.06 270 bottom
R79725  470R2J-2-GP  [R402H16]  138.95 35 270 bottom
R79726  470R2J-2-GP  [R402H16]  138.95 28.14 270 bottom
R79727  470R2J-2-GP  [R402H16]  138.95 38.94 270 bottom
R79728  470R2J-2-GP  [R402H16]  138.95 32.08 270 bottom
R79729  470R2J-2-GP  [R402H16]  138.95 36.02 270 bottom
R79730  470R2J-2-GP  [R402H16]  138.89 42.85 270 bottom
R79731  470R2J-2-GP  [R402H16]  138.95 39.95 270 bottom
R79732  2K2R2J-2-GP  [R402H16]  130.22 29.41 270 top
R79733  2K2R2J-2-GP  [R402H16]  128.24 29.41 90 top
R79734  4K7R2F-GP  [R402H16]  131.72 41.54 0 bottom
R79735  4K7R2F-GP  [R402H16]  131.72 41.54 0 top
R79736  2K2R2J-2-GP  [R402H16]  134.9 29.62 180 top
R79737  2K2R2J-2-GP  [R402H16]  135.94 29.62 180 top
R79738  2K2R2J-2-GP  [R402H16]  128.24 30.56 270 top
R79739  2K2R2J-2-GP  [R402H16]  130.22 30.56 90 top
R79741  4K7R2F-GP  [R402H16]  132.28 28.3 90 top
R79742  4K7R2F-GP  [R402H16]  132.28 27.18 270 top
R79743  4K7R2F-GP  [R402H16]  133.78 41.54 0 bottom
R79744  4K7R2F-GP  [R402H16]  133.78 41.54 0 top
R79745  4K7R2F-GP  [R402H16]  132.74 41.54 0 bottom
R79746  4K7R2F-GP  [R402H16]  132.74 41.54 0 top
R79747  4D3KR2F-GP  [R402H16]  130.71 41.54 180 top
R79748  4K7R2F-GP  [R402H16]  128.78 41.54 0 top
R79749  4K7R2F-GP  [R402H16]  134.9 41.54 0 top
R79750  10KR2J-3-GP  [R402H16]  129.9 22.86 0 bottom
R79751  180R3F-GP  [R603H22]  123.45 18.82 270 bottom
R79752  36R3F-GP  [R603H22]  126.27 19.18 270 bottom
R79753  0R3J-0-U-GP  [R603H22]  159.75 192.68 90 bottom
R79754  10KR5F-2-GP  [R805H24]  25.56 10.97 270 bottom
R79755  0R2J-2-GP  [R402H16]  54.45 136.52 90 top
R79756  0R2J-2-GP  [R402H16]  89.09 77.14 180 top
R79757  100KR2J-1-GP  [R402H16]  16.02 187.71 180 top
R79758  10KR2J-3-GP  [R402H16]  44.66 119.93 0 bottom
R79759  1KR2J-1-GP  [R402H16]  135.24 55.73 90 top
R79761  1KR2J-1-GP  [R402H16]  135.03 54.23 180 top
R79762  1KR2J-1-GP  [R402H16]  135.08 57.81 90 top
R79763  1KR2J-1-GP  [R402H16]  135.08 56.77 90 top
R79764  2K2R2J-2-GP  [R402H16]  92.46 36.2 90 top
R79765  10KR2J-3-GP  [R402H16]  91.55 37.85 0 top
R79766  1KR2J-1-GP  [R402H16]  129.04 46.81 0 top
R79772  1KR2J-1-GP  [R402H16]  138.5 63.04 90 top
R79773  10KR2J-3-GP  [R402H16]  128.96 60.33 0 bottom
R79774  20KR2J-L2-GP  [R402H16]  136.58 66.12 180 top
R79780  10KR2F-2-GP  [R402H16]  127.92 60.33 0 bottom
R79781  10KR2J-3-GP  [R402H16]  110.32 57.51 0 top
R79785  113R2F-GP  [R402H16]  66.68 176.56 270 top
R79786  20KR2J-L2-GP  [R402H16]  83.52 209.19 0 bottom
R79787  100R2F-L1-GP-U  [R402H14]  82.82 172.85 180 bottom
R79788  100R2F-L1-GP-U  [R402H14]  75.53 155.43 180 bottom
R79790  200R2F-L-GP  [R402H16]  76.28 210.69 0 bottom
R79791  200R2F-L-GP  [R402H16]  78.77 181.53 180 bottom
R79792  200R2F-L-GP  [R402H16]  19.36 160.16 90 top
R79793  301R2F-GP  [R402H16]  18.98 164.58 270 top
R79794  301R2F-GP  [R402H16]  79.66 210.69 0 bottom
R79795  200R2F-L-GP  [R402H16]  75.71 208.74 0 bottom
R79796  47KR2F-GP  [R402H16]  99.25 222.85 180 top
R79797  10KR2J-3-GP  [R402H16]  69.08 160.58 0 bottom
R79798  2K2R2J-2-GP  [R402H16]  54.22 139.51 90 top
R79799  10KR2J-3-GP  [R402H16]  54.22 138.45 270 top
R79800  51KR2F-L-GP  [R402H16]  97.22 223.92 180 top
R79802  59KR2F-GP  [R402H16]  136.05 109.72 90 bottom
R79913  0R2J-2-GP  [R402H16]  22.79 193.5 270 bottom
R79914  4K7R2J-2-GP  [R402H16]  18.96 207.14 0 top
R79915  47KR2J-2-GP  [R402H16]  18.96 197.51 270 bottom
R79916  100KR2J-1-GP  [R402H16]  18.96 198.55 90 bottom
R79917  10KR2J-3-GP  [R402H16]  21.75 201.17 0 bottom
R79935  -  [0R0805-PAD]  21.24 206.32 180 top
R79936  10KR2J-3-GP  [R402H16]  20.28 193.5 270 bottom
R79937  200R2F-L-GP  [R402H16]  17.94 161.58 270 top
R79938  0R2J-2-GP  [R402H16]  119.64 61.57 90 bottom
R79939  0R0402-PAD-2-GP  [0R0402-PAD-1]  120.98 69.65 0 top
R79940  33R2J-2-GP  [R402H16]  47.87 71.43 90 bottom
R79941  33R2J-2-GP  [R402H16]  47.87 70.39 90 bottom
R79942  33R2J-2-GP  [R402H16]  32.14 65.37 180 bottom
R79943  10KR2J-3-GP  [R402H16]  157.56 106.32 0 bottom
R79944  10KR2J-3-GP  [R402H16]  157.13 181.79 0 top
R79945  10KR2J-3-GP  [R402H16]  123.25 64.49 270 bottom
R79946  0R2J-2-GP  [R402H16]  143.19 61.14 0 top
R79947  0R2J-2-GP  [R402H16]  129.83 55.24 270 bottom
R79948  0R2J-2-GP  [R402H16]  113.34 62.66 180 top
R79949  0R0402-PAD-2-GP  [0R0402-PAD-1]  14.96 224.08 90 top
R79950  0R0402-PAD-2-GP  [0R0402-PAD-1]  114.56 55.5 0 bottom
R79951  0R2J-2-GP  [R402H16]  122.11 69.62 0 top
R79952  10KR2J-3-GP  [R402H16]  123.47 58.54 0 bottom
R79953  10KR2J-3-GP  [R402H16]  124.51 58.54 0 bottom
R79954  0R2J-2-GP  [R402H16]  145.58 84.12 270 top
R79955  0R2J-2-GP  [R402H16]  145.58 85.14 270 top
R79956  0R2J-2-GP  [R402H16]  145.58 86.21 270 top
R79957  0R2J-2-GP  [R402H16]  150.22 77.85 180 top
R79960  0R2J-2-GP  [R402H16]  145.6 87.25 270 top
R79961  0R2J-2-GP  [R402H16]  145.6 88.29 270 top
R79962  47R2J-2-GP  [R402H16]  84.13 87.99 180 bottom
R79963  8K45R2F-2-GP  [R402H16]  95.27 101.98 270 bottom
R79964  0R2J-2-GP  [R402H16]  98.71 91.19 90 top
R79965  10KR2J-L-GP  [R402H15]  80.47 83.14 180 bottom
R79966  47KR2F-GP  [R402H16]  99.61 87.95 270 top
R79967  2K2R2J-2-GP  [R402H16]  100.11 89.41 180 top
R79968  2K1R2F-GP  [R402H16]  48.76 96.15 180 top
R79977  0R0402-PAD-2-GP  [0R0402-PAD-1]  163.38 135.25 270 top
R79980  0R0402-PAD-2-GP  [0R0402-PAD-1]  163.15 137.13 270 top
R79981  0R0402-PAD-2-GP  [0R0402-PAD-1]  162.82 153.11 90 top
R79982  0R0402-PAD-2-GP  [0R0402-PAD-1]  162.82 151.71 90 top
R80049  20KR2F-L-GP  [R402H16]  144.15 116.43 180 top
R80050  0R0402-PAD-2-GP  [0R0402-PAD-1]  141.66 113.39 270 top
R80051  0R0402-PAD-2-GP  [0R0402-PAD-1]  145.17 114.71 270 bottom
R80052  0R0402-PAD-2-GP  [0R0402-PAD-1]  141.66 112.34 270 top
R80053  0R0402-PAD-2-GP  [0R0402-PAD-1]  145.19 113.67 270 bottom
R80054  0R2J-2-GP  [R402H16]  160.79 133.99 180 top
R80055  0R2J-2-GP  [R402H16]  160.74 131.98 90 top
R80056  0R2J-2-GP  [R402H16]  160.94 151.38 180 top
R80057  0R2J-2-GP  [R402H16]  160.97 147.9 180 top
R80059  0R2J-2-GP  [R402H16]  141.81 109.17 270 top
R80060  33KR2F-GP  [R402H16]  145.19 117.3 180 top
R80061  0R2J-2-GP  [R402H16]  146.24 116.64 180 top
R80062  10KR2J-3-GP  [R402H16]  144.56 108.92 0 top
R80063  0R2J-2-GP  [R402H16]  145.04 105.98 270 top
R80064  0R2J-2-GP  [R402H16]  146.99 106.94 0 top
R80065  0R2J-2-GP  [R402H16]  147.76 108.92 0 top
R80074  0R2J-2-GP  [R402H16]  49.07 137.6 180 top
R80075  0R2J-2-GP  [R402H16]  48 137.6 180 top
R80076  0R2J-2-GP  [R402H16]  46.91 137.6 180 top
R80077  0R2J-2-GP  [R402H16]  45.86 137.6 180 top
R80078  0R2J-2-GP  [R402H16]  47.75 134.3 0 bottom
R80079  0R2J-2-GP  [R402H16]  48.89 134.3 0 bottom
R80080  0R2J-2-GP  [R402H16]  45.54 134.33 0 bottom
R80081  0R2J-2-GP  [R402H16]  46.68 134.33 0 bottom
R80090  0R2J-2-GP  [R402H16]  51.24 134.29 0 bottom
R80091  0R2J-2-GP  [R402H16]  50.06 134.29 0 bottom
R80092  0R0402-PAD-2-GP  [0R0402-PAD-1]  132.27 32.05 270 bottom
R80093  0R0402-PAD-2-GP  [0R0402-PAD-1]  134.81 29.64 0 bottom
R80099  0R2J-2-GP  [R402H16]  51.18 137.6 0 top
R80100  0R2J-2-GP  [R402H16]  50.12 137.6 0 top
R80102  100KR2F-L1-GP  [R402H16]  43.29 222.12 90 top
R80103  0R0402-PAD-2-GP  [0R0402-PAD-1]  163.23 147.88 0 top
R80104  0R0402-PAD-2-GP  [0R0402-PAD-1]  163.28 138.68 270 top
R80105  0R0402-PAD-2-GP  [0R0402-PAD-1]  163.38 132.11 90 top
R80106  0R0402-PAD-2-GP  [0R0402-PAD-1]  163.3 156.11 180 top
R80107  0R2J-2-GP  [R402H16]  160.17 143.63 180 top
R80108  0R2J-2-GP  [R402H16]  160.75 136.68 180 top
R80109  0R2J-2-GP  [R402H16]  160.05 130.35 90 top
R80110  2K2R2J-2-GP  [R402H16]  129.81 28.76 180 bottom
R80111  2K2R2J-2-GP  [R402H16]  133.77 26.71 180 bottom
R80112  1MR2J-1-GP  [R402H16]  127.63 41.08 0 top
R80113  0R2J-2-GP  [R402H16]  125.45 41.08 0 top
R80115  0R2J-2-GP  [R402H16]  81.92 122.31 180 top
R80116  10KR2J-3-GP  [R402H16]  80.4 122.74 90 top
R80120  100KR2J-1-GP  [R402H16]  65.15 141.73 0 top
R80121  10KR2J-3-GP  [R402H16]  77.27 134.32 90 top
R80122  0R2J-2-GP  [R402H16]  141.13 82.1 180 top
R80123  0R2J-2-GP  [R402H16]  150.39 73.69 180 top
R80124  10KR5F-2-GP  [R805H24]  23.83 16 270 top
R80125  10KR2F-2-GP  [R402H16]  145.25 73.58 270 bottom
R80126  10KR2F-2-GP  [R402H16]  143.19 71.09 270 bottom
R80128  100KR2F-L1-GP  [R402H16]  147.11 70.25 90 bottom
R80130  57K6R2D-GP  [R402H16]  147.93 72.5 270 bottom
R80132  0R2J-2-GP  [R402H16]  142.4 80.73 180 top
R80133  47KR2F-GP  [R402H16]  145.31 72.26 90 bottom
R80134  0R2J-2-GP  [R402H16]  43.92 114.58 180 top
R80137  499R2F-2-GP  [R402H16]  92.48 106.34 270 bottom
R80138  0R0603-PAD-2-GP-U  [0R0603-PAD-1-U]  90.03 110.52 90 bottom
R80139  0R0603-PAD-2-GP-U  [0R0603-PAD-1-U]  88.07 109.77 0 bottom
R80140  4K7R2J-2-GP  [R402H16]  92.41 110.37 270 bottom
R80141  4K7R2J-2-GP  [R402H16]  92.41 109.33 270 bottom
R80142  4K7R2J-2-GP  [R402H16]  98.36 105.3 90 top
R80143  150R2F-1-GP  [R402H16]  90.76 100.47 90 bottom
R80144  10KR2J-3-GP  [R402H16]  66.7 141.79 90 top
R80145  100KR2J-1-GP  [R402H16]  66.8 140.72 270 top
R80146  10KR2J-3-GP  [R402H16]  77.62 136.77 0 top
R80147  0R2J-2-GP  [R402H16]  65.47 174.4 180 top
R80148  0R3J-0-U-GP  [R603H22]  69.76 144.15 180 top
R80149  49D9R2F-GP  [R402H16]  67.08 174.53 270 top
R80150  10KR2J-3-GP  [R402H16]  69.47 133.61 0 top
R80151  0R3J-0-U-GP  [R603H22]  77.62 129.78 180 top
R80152  0R3J-0-U-GP  [R603H22]  77.61 132.45 180 top
R80153  0R0402-PAD-2-GP  [0R0402-PAD-1]  71.55 143.9 90 top
R80154  0R0402-PAD-2-GP  [0R0402-PAD-1]  68.7 141.79 90 top
R80155  1KR2J-1-GP  [R402H16]  85.1 123.14 270 top
R80156  0R2J-2-GP  [R402H16]  160.3 154.48 180 top
R80157  20KR2J-L2-GP  [R402H16]  131.2 44.12 270 top
R80201  4K7R2J-2-GP  [R402H16]  140.39 6.02 180 top
R80202  4K7R2J-2-GP  [R402H16]  139.33 6.02 180 top
R80203  0R2J-2-GP  [R402H16]  142.92 75.45 270 bottom
R80204  0R2J-2-GP  [R402H16]  135.45 67.73 90 bottom
R80205  0R2J-2-GP  [R402H16]  134.96 69.85 90 bottom
R80206  0R2J-2-GP  [R402H16]  124.29 47.09 180 top
R80207  0R2J-2-GP  [R402H16]  116.8 47.9 90 top
R80208  0R2J-2-GP  [R402H16]  115.04 48.01 180 top
R80209  0R2J-2-GP  [R402H16]  113.57 48.44 90 top
R80210  0R2J-2-GP  [R402H16]  112.88 49.69 90 top
R80211  0R2J-2-GP  [R402H16]  137.37 68.4 0 top
R80212  10KR2J-3-GP  [R402H16]  139.2 68.2 270 top
R80215  15KR2F-GP  [R402H16]  110.93 52.53 270 top
R80216  10KR2F-2-GP  [R402H16]  112.07 51.51 90 top
R80217  10KR2J-3-GP  [R402H16]  126.3 53.37 0 bottom
R80218  0R2J-2-GP  [R402H16]  123.25 47.09 180 top
R80219  10KR2J-3-GP  [R402H16]  40.48 116.08 90 top
R80220  10KR2J-3-GP  [R402H16]  40.51 114.99 90 top
R80228  8K2R2J-3-GP  [R402H16]  134.49 72.17 0 bottom
R80229  39K2R2F-L-GP  [R402H16]  135.96 71.58 270 bottom
R80230  10KR2J-3-GP  [R402H16]  146.22 75.91 180 bottom
R80231  0R2J-2-GP  [R402H16]  125.34 66.21 180 bottom
